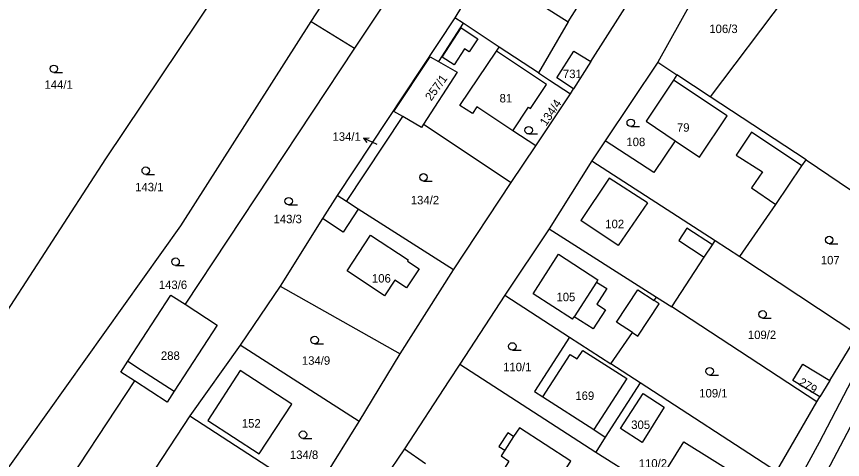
# Model space of a CAD drawing. Extents: x -747333 to -743907, y -1134120 to -1130051.
# Drawn here: x -746336.6 to -746170.7, y -1131729.3 to -1131640.4 of the extents above; entities that cross this region are included whole.
import ezdxf

# ---------------------------------------------------------------- set-up
doc = ezdxf.new("R2010")
doc.units = 0
for name, color, linetype in [('Hranice parcel', 7, 'Continuous'), ('Parcelní čísla', 7, 'Continuous'), ('Pop  PČ popisy', 7, 'Continuous'), ('Vnitřní kresba', 7, 'Continuous'), ('Značky kultur', 7, 'Continuous')]:
    doc.layers.add(name, color=color, linetype=linetype)

msp = doc.modelspace()

# ---------------------------------------------------------------- linework, layer by layer
at = {"layer": 'Hranice parcel'}
for p, q in [((-746226.17, -1131603.55), (-746248.59, -1131640.59)), ((-746277.47, -1131641.33), (-746267.12, -1131625.65)), ((-746178.11, -1131631.02), (-746197.29, -1131656.44)), ((-746248.59, -1131640.59), (-746272.19, -1131676.27)), ((-746246.92, -1131641.69), (-746248.59, -1131640.59)), ((-746277.47, -1131641.33), (-746268.75, -1131646.7)), ((-746246.92, -1131641.69), (-746251.87, -1131649.36)), ((-746239.66, -1131646.47), (-746246.92, -1131641.69)), ((-746225.82, -1131641.41), (-746231.78, -1131651.66)), ((-746268.75, -1131646.7), (-746302.76, -1131698.11)), ((-746231.78, -1131651.66), (-746239.66, -1131646.47)), ((-746260.8, -1131659.43), (-746253.51, -1131648.41)), ((-746253.51, -1131648.41), (-746251.87, -1131649.36)), ((-746221.25, -1131649.38), (-746224.73, -1131654.87)), ((-746207.82, -1131649.53), (-746218.4, -1131665.32)), ((-746207.82, -1131649.53), (-746203.97, -1131652.06)), ((-746203.97, -1131652.06), (-746204.68, -1131653.13)), ((-746197.29, -1131656.44), (-746203.97, -1131652.06)), ((-746232.33, -1131666.33), (-746225.37, -1131655.87)), ((-746225.37, -1131655.87), (-746224.73, -1131654.87)), ((-746178.01, -1131669.1), (-746197.29, -1131656.44)), ((-746270.36, -1131677.49), (-746259.04, -1131660.44)), ((-746259.04, -1131660.44), (-746260.8, -1131659.43)), ((-746254.86, -1131661.98), (-746237.23, -1131673.69)), ((-746218.4, -1131665.32), (-746221.07, -1131669.31)), ((-746208.6, -1131671.63), (-746218.4, -1131665.32)), ((-746237.23, -1131673.69), (-746232.33, -1131666.33)), ((-746178.84, -1131670.33), (-746178.01, -1131669.1)), ((-746178.01, -1131669.1), (-746154.22, -1131685.29)), ((-746221.07, -1131669.31), (-746229.64, -1131682.94)), ((-746221.07, -1131669.31), (-746196.29, -1131685.32)), ((-746184.1, -1131678.09), (-746178.84, -1131670.33)), ((-746248.85, -1131691.18), (-746237.23, -1131673.69)), ((-746270.36, -1131677.49), (-746272.19, -1131676.27)), ((-746268.02, -1131679.05), (-746270.36, -1131677.49)), ((-746248.85, -1131691.18), (-746268.02, -1131679.05)), ((-746191.3, -1131688.55), (-746184.1, -1131678.09)), ((-746229.64, -1131682.94), (-746238.54, -1131696.32)), ((-746229.64, -1131682.94), (-746208.05, -1131696.69)), ((-746196.84, -1131686.16), (-746196.29, -1131685.32)), ((-746196.29, -1131685.32), (-746191.3, -1131688.55)), ((-746198.48, -1131688.67), (-746196.84, -1131686.16)), ((-746205.01, -1131698.62), (-746198.48, -1131688.67)), ((-746191.3, -1131688.55), (-746167.6, -1131704.18)), ((-746259.58, -1131708.06), (-746248.85, -1131691.18)), ((-746283.65, -1131694.51), (-746291.7, -1131706.32)), ((-746283.65, -1131694.51), (-746259.58, -1131708.06)), ((-746305.6, -1131696.26), (-746302.76, -1131698.11)), ((-746238.54, -1131696.32), (-746247.57, -1131710.13)), ((-746238.54, -1131696.32), (-746225.54, -1131704.73)), ((-746208.05, -1131696.69), (-746205.01, -1131698.62)), ((-746302.76, -1131698.11), (-746296.31, -1131702.3)), ((-746211.79, -1131704.5), (-746207.53, -1131698.01)), ((-746175.84, -1131717.7), (-746205.01, -1131698.62)), ((-746225.54, -1131704.73), (-746232.57, -1131715.63)), ((-746225.54, -1131704.73), (-746217.23, -1131710.1)), ((-746173.21, -1131713.39), (-746167.6, -1131704.18)), ((-746291.7, -1131706.32), (-746301.83, -1131720.48)), ((-746267.83, -1131721.62), (-746291.7, -1131706.32)), ((-746267.83, -1131721.62), (-746259.58, -1131708.06)), ((-746247.57, -1131710.13), (-746220.28, -1131727.78)), ((-746211.35, -1131713.91), (-746217.23, -1131710.1)), ((-746180.67, -1131713.43), (-746178.65, -1131710.15)), ((-746178.65, -1131710.15), (-746173.21, -1131713.39)), ((-746312.93, -1131713.49), (-746315.66, -1131711.72)), ((-746306.37, -1131717.75), (-746312.93, -1131713.49)), ((-746211.35, -1131713.91), (-746218.35, -1131724.78)), ((-746183.97, -1131731.72), (-746211.35, -1131713.91)), ((-746175.23, -1131716.7), (-746180.67, -1131713.43)), ((-746173.21, -1131713.39), (-746175.23, -1131716.7)), ((-746175.84, -1131717.7), (-746175.23, -1131716.7)), ((-746183.97, -1131731.72), (-746175.84, -1131717.7)), ((-746301.83, -1131720.48), (-746311.89, -1131735.77)), ((-746301.83, -1131720.48), (-746277.08, -1131736.51)), ((-746277.08, -1131736.51), (-746267.83, -1131721.62)), ((-746220.68, -1131723.28), (-746218.35, -1131724.78)), ((-746218.35, -1131724.78), (-746220.28, -1131727.78)), ((-746258.71, -1131727.17), (-746264.78, -1131736.1)), ((-746258.71, -1131727.17), (-746254.46, -1131730.08)), ((-746220.28, -1131727.78), (-746191.89, -1131745.5))]:
    msp.add_line(p, q, dxfattribs=at)
for points in [[(-746221.25, -1131649.38), (-746209.49, -1131630.87), (-746190.58, -1131600.07), (-746179.04, -1131577.6), (-746173.33, -1131568.01)], [(-746196.48, -1131579.32), (-746203.74, -1131591.04), (-746207.17, -1131588.88), (-746236.19, -1131634.81), (-746225.82, -1131641.41)], [(-746225.82, -1131641.41), (-746196.77, -1131595.45), (-746188.95, -1131583.07)], [(-746251.98, -1131620.08), (-746256.41, -1131628.18), (-746268.75, -1131646.7)], [(-746209.77, -1131799.39), (-746188.47, -1131759.43), (-746165.71, -1131716.39), (-746153.65, -1131693.34), (-746142.41, -1131673.43), (-746130.42, -1131652.96), (-746119.1, -1131634.98), (-746122.9, -1131621.67)], [(-746192.62, -1131623.6), (-746200.96, -1131637.27), (-746207.82, -1131649.53)], [(-746292.81, -1131630.24), (-746318.73, -1131668.93), (-746345.52, -1131710.16)], [(-746342.61, -1131738.39), (-746337.96, -1131730.57), (-746303.62, -1131682.4), (-746277.47, -1131641.33)], [(-746232.33, -1131666.33), (-746236.91, -1131663.29), (-746233.75, -1131658.54), (-746233.36, -1131658.8), (-746230.15, -1131654.01), (-746240.2, -1131647.27), (-746239.66, -1131646.47)], [(-746224.73, -1131654.87), (-746228.08, -1131652.63), (-746224.65, -1131647.29), (-746221.25, -1131649.38)], [(-746251.87, -1131649.36), (-746248.14, -1131651.53), (-746254.86, -1131661.98)], [(-746231.78, -1131651.66), (-746229.55, -1131653.12), (-746225.37, -1131655.87)], [(-746204.68, -1131653.13), (-746210.15, -1131661.38), (-746204.34, -1131665.28), (-746208.6, -1131671.63)], [(-746254.86, -1131661.98), (-746255.27, -1131662.62), (-746259.04, -1131660.44)], [(-746272.19, -1131676.27), (-746275.18, -1131680.92), (-746283.65, -1131694.51)], [(-746154.22, -1131685.29), (-746175.35, -1131725.88), (-746198.19, -1131767.85), (-746214.17, -1131798.54), (-746227.58, -1131820.8), (-746249.27, -1131852.92), (-746268.11, -1131879.9), (-746296.61, -1131921.49), (-746301.25, -1131926.61)], [(-746315.66, -1131711.72), (-746314.24, -1131709.54), (-746305.6, -1131696.26)], [(-746207.53, -1131698.01), (-746208.52, -1131697.37), (-746208.05, -1131696.69)], [(-746296.31, -1131702.3), (-746304.95, -1131715.57), (-746306.37, -1131717.75)], [(-746217.23, -1131710.1), (-746212.9, -1131703.77), (-746211.79, -1131704.5)], [(-746247.57, -1131710.13), (-746249.77, -1131713.5), (-746258.71, -1131727.17)], [(-746298.18, -1131721.44), (-746287.86, -1131728.15), (-746281.34, -1131718.15), (-746291.72, -1131711.44), (-746298.18, -1131721.44)], [(-746312.93, -1131713.49), (-746329.64, -1131738.75), (-746326.66, -1131740.92)], [(-746232.57, -1131715.63), (-746230.88, -1131716.72), (-746220.68, -1131723.28)], [(-746206.49, -1131718.76), (-746210.97, -1131725.86), (-746215.29, -1131723.08), (-746210.77, -1131716.05), (-746206.49, -1131718.76)], [(-746230.93, -1131738.3), (-746225.29, -1131729.6), (-746235.61, -1131722.9), (-746236.77, -1131724.69), (-746237.95, -1131723.93), (-746239.73, -1131726.67), (-746238.56, -1131727.43), (-746239.28, -1131728.55), (-746237.75, -1131729.59), (-746239.58, -1131732.69), (-746230.93, -1131738.3)], [(-746199.96, -1131737.11), (-746200.56, -1131738.06), (-746203.72, -1131736.08), (-746207.52, -1131733.7), (-746202.54, -1131725.73), (-746191.73, -1131732.48), (-746196.12, -1131739.51), (-746199.96, -1131737.11)]]:
    msp.add_lwpolyline(points, dxfattribs=at)
at = {"layer": 'Pop  PČ popisy'}
for p, q in [((-746266.93, -1131664.762), (-746265.811, -1131664.731)), ((-746264.21, -1131666.03), (-746266.93, -1131664.762)), ((-746266.93, -1131664.762), (-746266.234, -1131665.639))]:
    msp.add_line(p, q, dxfattribs=at)
at = {"layer": 'Vnitřní kresba'}
for p, q in [((-746251.15, -1131648.49), (-746247.31, -1131642.64)), ((-746247.31, -1131642.64), (-746243.97, -1131644.83)), ((-746243.97, -1131644.83), (-746245.7, -1131647.47)), ((-746246.61, -1131646.86), (-746248.73, -1131650.08)), ((-746247.54, -1131658.2), (-746240.2, -1131647.27)), ((-746245.7, -1131647.47), (-746246.61, -1131646.86)), ((-746248.73, -1131650.08), (-746251.15, -1131648.49)), ((-746193.87, -1131660.27), (-746204.68, -1131653.13)), ((-746245.06, -1131659.85), (-746247.54, -1131658.2)), ((-746244.15, -1131658.48), (-746245.06, -1131659.85)), ((-746236.91, -1131663.29), (-746244.15, -1131658.48)), ((-746199.42, -1131668.58), (-746193.87, -1131660.27)), ((-746188.96, -1131663.55), (-746192.08, -1131668.2)), ((-746178.84, -1131670.33), (-746188.96, -1131663.55)), ((-746204.34, -1131665.28), (-746199.42, -1131668.58)), ((-746192.08, -1131668.2), (-746186.79, -1131671.5)), ((-746186.79, -1131671.5), (-746189, -1131674.77)), ((-746217.55, -1131672.77), (-746223.27, -1131681.3)), ((-746209.89, -1131677.72), (-746217.55, -1131672.77)), ((-746189, -1131674.77), (-746184.1, -1131678.09)), ((-746268.02, -1131679.05), (-746271.01, -1131683.64)), ((-746209.89, -1131677.72), (-746215.75, -1131686.34)), ((-746271.01, -1131683.64), (-746275.18, -1131680.92)), ((-746215.75, -1131686.34), (-746223.27, -1131681.3)), ((-746270.22, -1131691.39), (-746265.49, -1131684.21)), ((-746265.49, -1131684.21), (-746257.93, -1131689.19)), ((-746201.94, -1131682.81), (-746203.59, -1131685.32)), ((-746196.84, -1131686.16), (-746201.94, -1131682.81)), ((-746203.59, -1131685.32), (-746198.48, -1131688.67)), ((-746257.93, -1131689.19), (-746258.1, -1131689.44)), ((-746232.86, -1131696.03), (-746227.77, -1131688.09)), ((-746227.77, -1131688.09), (-746219.83, -1131693.18)), ((-746258.1, -1131689.44), (-746255.76, -1131690.98)), ((-746262.72, -1131696.4), (-746270.22, -1131691.39)), ((-746255.76, -1131690.98), (-746258.29, -1131694.82)), ((-746260.66, -1131693.3), (-746262.72, -1131696.4)), ((-746258.29, -1131694.82), (-746260.66, -1131693.3)), ((-746220.13, -1131693.65), (-746224.59, -1131700.61)), ((-746219.83, -1131693.18), (-746220.13, -1131693.65)), ((-746220.13, -1131693.65), (-746218.05, -1131694.98)), ((-746218.05, -1131694.98), (-746220.04, -1131698.08)), ((-746216.08, -1131701.68), (-746211.84, -1131695.22)), ((-746211.84, -1131695.22), (-746208.52, -1131697.37)), ((-746224.92, -1131701.12), (-746232.86, -1131696.03)), ((-746220.04, -1131698.08), (-746218.3, -1131699.2)), ((-746224.92, -1131701.12), (-746224.59, -1131700.61)), ((-746220.81, -1131703.03), (-746224.59, -1131700.61)), ((-746218.3, -1131699.2), (-746220.81, -1131703.03)), ((-746212.9, -1131703.77), (-746216.08, -1131701.68)), ((-746223.99, -1131709.08), (-746222.85, -1131707.37)), ((-746222.85, -1131707.37), (-746214.04, -1131713.03)), ((-746230.88, -1131716.72), (-746225.39, -1131708.18)), ((-746225.39, -1131708.18), (-746223.99, -1131709.08)), ((-746314.24, -1131709.54), (-746311.5, -1131711.32)), ((-746311.5, -1131711.32), (-746304.95, -1131715.57)), ((-746214.04, -1131713.03), (-746220.68, -1131723.28)), ((-746236.77, -1131724.69), (-746238.56, -1131727.43))]:
    msp.add_line(p, q, dxfattribs=at)
at = {"layer": 'Značky kultur'}
for p, q in [((-746329.133, -1131651.59), (-746327.383, -1131651.59)), ((-746213.233, -1131662.43), (-746211.483, -1131662.43)), ((-746233.743, -1131663.93), (-746231.993, -1131663.93)), ((-746310.673, -1131672.04), (-746308.923, -1131672.04)), ((-746254.873, -1131673.38), (-746253.123, -1131673.38)), ((-746281.963, -1131678.17), (-746280.213, -1131678.17)), ((-746173.373, -1131685.96), (-746171.623, -1131685.96)), ((-746304.683, -1131690.32), (-746302.933, -1131690.32)), ((-746186.753, -1131700.89), (-746185.003, -1131700.89)), ((-746276.743, -1131706.05), (-746274.993, -1131706.05)), ((-746237.023, -1131707.33), (-746235.273, -1131707.33)), ((-746197.383, -1131712.32), (-746195.633, -1131712.32)), ((-746279.083, -1131725.04), (-746277.333, -1131725.04))]:
    msp.add_line(p, q, dxfattribs=at)
for centre in [(-746329.133, -1131650.84), (-746213.233, -1131661.68), (-746233.743, -1131663.18), (-746310.673, -1131671.29), (-746254.873, -1131672.63), (-746281.963, -1131677.42), (-746173.373, -1131685.21), (-746304.683, -1131689.57), (-746186.753, -1131700.14), (-746276.743, -1131705.3), (-746237.023, -1131706.58), (-746197.383, -1131711.57), (-746279.083, -1131724.29)]:
    msp.add_circle(centre, 0.75, dxfattribs=at)

# ---------------------------------------------------------------- texts
at = {"layer": 'Parcelní čísla'}
for s, p in [('106/3', (-746197.45, -1131643.67)), ('731', (-746226.864, -1131652.71)), ('144/1', (-746331.01, -1131654.86)), ('81', (-746239.59, -1131657.6)), ('79', (-746203.96, -1131663.48)), ('134/1', (-746273.156, -1131665.3)), ('108', (-746214.11, -1131666.37)), ('143/1', (-746312.8, -1131675.44)), ('134/2', (-746257.43, -1131678.06)), ('143/3', (-746285, -1131681.85)), ('102', (-746218.35, -1131682.84)), ('107', (-746175.06, -1131690.11)), ('106', (-746265.23, -1131693.76)), ('143/6', (-746308.05, -1131695.06)), ('105', (-746228.16, -1131697.5)), ('109/2', (-746189.71, -1131705.1)), ('288', (-746307.624, -1131709.28)), ('134/9', (-746279.31, -1131710.26)), ('110/1', (-746238.88, -1131711.56)), ('169', (-746224.37, -1131717.32)), ('109/1', (-746199.47, -1131716.82)), ('152', (-746291.37, -1131722.87)), ('305', (-746213.144, -1131723.15)), ('134/8', (-746281.71, -1131729.18)), ('110/2', (-746211.63, -1131730.92))]:
    msp.add_text(s, height=1.7, dxfattribs=at).set_placement(p)
for s, rotation, p in [('257/1', 54, (-746253.322, -1131657.413)), ('134/4', 56, (-746230.235, -1131662.455)), ('279', 329, (-746179.68, -1131714.201))]:
    msp.add_text(s, height=1.7, rotation=rotation, dxfattribs=at).set_placement(p)

doc.saveas('drawing.dxf')
